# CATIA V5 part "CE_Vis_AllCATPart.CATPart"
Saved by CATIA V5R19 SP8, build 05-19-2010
Part number: CE5_Vis_AllCATPart
Bounding box of the stored display mesh (mm): x -62 to -4, y 90.221 to 186.093, z 3.957 to 130.324
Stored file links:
  D:\Documents\1_Travail\1 - ac-limoges.fr\ac-limoges.fr\Emmanuel Maynard - STI2D_Turgot\2 -2I2D\1_SEQUENCE_ Tapis_de_course\3- Spécificités\Spé_ITEC\3-Pente\Tapis_TC520B_Pente\CE_Vis_AllCATPart.CATPart
  D:\Documents\1_Travail\1 - ac-limoges.fr\ac-limoges.fr\Emmanuel Maynard - STI2D_Turgot\2 -2I2D\1_SEQUENCE_ Tapis_de_course\3- Spécificités\Spé_ITEC\3-Pente\Tapis_TC520B_Pente\0_Tapis_TC520B_Simulation.CATProduct
  D:\Documents\1_Travail\1 - ac-limoges.fr\ac-limoges.fr\Emmanuel Maynard - STI2D_Turgot\2 -2I2D\1_SEQUENCE_ Tapis_de_course\3- Spécificités\Spé_ITEC\3-Pente\Tapis_TC520B_Pente\CE_Chassis_AllCATPart.CATPart
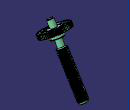
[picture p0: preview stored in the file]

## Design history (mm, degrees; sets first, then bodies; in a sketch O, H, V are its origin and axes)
AxisSystem1: origin (0, 0, 0), X (1, 0, 0), Y (0, 1, 0), Z (0, 0, 1)
Set1
  Plane1: stored without definition
Body1 (main body)
  Plane2: type 3Points, Element1 {point type Center, Curve edge [face of Solid2 | face of Solid2]}, Element2 {point type Center, Curve edge [face of Solid2 | face of Solid2]}, Element3 {point type Center, Curve edge [face of Solid1 | face of Solid1]}
  Sketch1 on Plane2, origin (-58.7924, 135.7996, 82.9814), H (-0.98, -0.0583, 0.1904), V (0.1926, -0.5199, 0.8322)
    point P1 (-28.0319, -8.7154)
    reference projected line E1 through (-25.3406, 4.9798) direction (-0.1928, -0.9812) from axis of face of Solid2
    coincidence: P1 E1
Body2 "Roue_4.1\\Corps principal"
  Solid1: solid without history
Body3 "Vis.5\\Corps principal"
  Solid2 "Solide.1": solid without history
Body4 "Flasque_ButéeAiguilles.3\\Corps principal"
  Solid3 "Solide.1": solid without history
Body5 "Axe_Vis.1\\Corps principal"
  Solid4 "Solide.1": solid without history
Body6 "Flasque_ButéeAiguilles.4\\Corps principal"
  Solid5 "Solide.1": solid without history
